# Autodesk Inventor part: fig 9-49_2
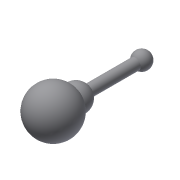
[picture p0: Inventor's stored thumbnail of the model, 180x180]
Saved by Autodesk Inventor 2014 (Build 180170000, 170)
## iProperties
Created: 2013-03
Part Number: fig 9-49_2
Material: Generic
Document SubType Name: Modeling
Designer: CADCIM
Density: 1 g/cm^3
Appearance: Default
Author: CADCIM
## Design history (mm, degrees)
sketch "Sketch1"
  geometry: L1 (0, 5)-(0, -5); A1 r 5 centre (0, 0) between (0, -5) and (0, 5); 1 further point
  constraints: 2 end point, 2 point on circle, 1 centre point, 1 coincident, 1 vertical
  dimensions: "d0" = 10 diameter of A1
revolve "Revolution1" sketch "Sketch1" stored, may be unused: angle "d2" = 90 deg
sketch "Sketch2"
  geometry: L1 (0, 20.921)-(0, 2.139); L2 (1.175, 7.426)-(1.175, 17.742); A1 r 1.807 centre (0, 19.115) between (1.175, 17.742) and (0, 20.921); A2 r 2.774 centre (0, 4.913) between (0, 2.139) and (1.175, 7.426); 1 further point
  constraints: 4 end point, 4 point on circle, 2 centre point, 1 parallel, 1 vertical
revolve "Revolution2" sketch "Sketch2" stored, may be unused: angle "d3" = 90 deg
body "Solid1"
